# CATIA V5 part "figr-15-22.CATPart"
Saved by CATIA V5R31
Part number: Part1
Bounding box of the stored display mesh (mm): x -75 to 76, y -66.397 to 33.603, z 0 to 100
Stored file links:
  D:\PROJECTS\Project 2021\US EDITION\CATIA V5 6R 2021\Resources\Part Files\c15_catia_v5_6r2021_prt\figr-15-22.CATPart
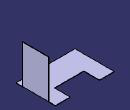
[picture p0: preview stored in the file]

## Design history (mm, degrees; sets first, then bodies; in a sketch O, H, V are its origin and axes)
SheetMetalParameters1: Thickness 1, BendRadius 1, KFactor 0.325257 {= log(min(100,max(20*SheetMetalParameters1.BendRadius,SheetMetalParameters1.Thickness)/SheetMetalParameters1.Thickness))/log(100)/2}, ReliefRadialLength 1, ReliefAxialLength 2, MinimumBendRadius 0
Body1 (main body)
  Sketch1 on xy-plane, origin (0, 0, 0), H (1, 0, 0), V (0, 1, 0)
    line L1 (-37.5, 33.6029) -> (-37.5, -6.3971)
    line L2 (-37.5, -6.3971) -> (37.5, -6.3971)
    line L3 (37.5, -6.3971) -> (37.5, 33.6029)
    line L4 (37.5, 33.6029) -> (75, 33.6029)
    line L5 (75, 33.6029) -> (75, -66.3971)
    line L6 (75, -66.3971) -> (-75, -66.3971)
    line L7 (-75, -66.3971) -> (-75, 33.6029)
    point P8 (-75, 33.6029)
    line L8 (-75, 33.6029) -> (-37.5, 33.6029)
    length L7 = 100
    length L1 = 40
    length L6 = 150
    distance L1 L3 = 75
    vertical: L1 V, L3 V, L5 V, L7 V
    horizontal: L2 H, L4 H, L6 H, L8 H
    coincidence: P8 L4
    symmetry: L7 L5 V, L1 L3 V
  Wall1: Thickness 1, Profile Sketch1
  d_NewWallOnEdge1: NewWallOnEdge_Edge edge [face of Wall1 | face of Wall1], NewWallOnEdge_Length 100, NewWallOnEdge_HeightLimitOffset 0, NewWallOnEdge_WidthOffset1 -16, NewWallOnEdge_WidthOffset2 -17, NewWallOnEdge_Angle 90, NewWallOnEdge_BendRadiusValue 1 {= SheetMetalParameters1.BendRadius}, NewWallOnEdge_BendTable SheetMetalParameters1, KFacteur 0.325257 {= log(min(100,max(20*d_NewWallOnEdge1.Radius,SheetMetalParameters1.Thickness)/SheetMetalParameters1.Thickness))/log(100)/2}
